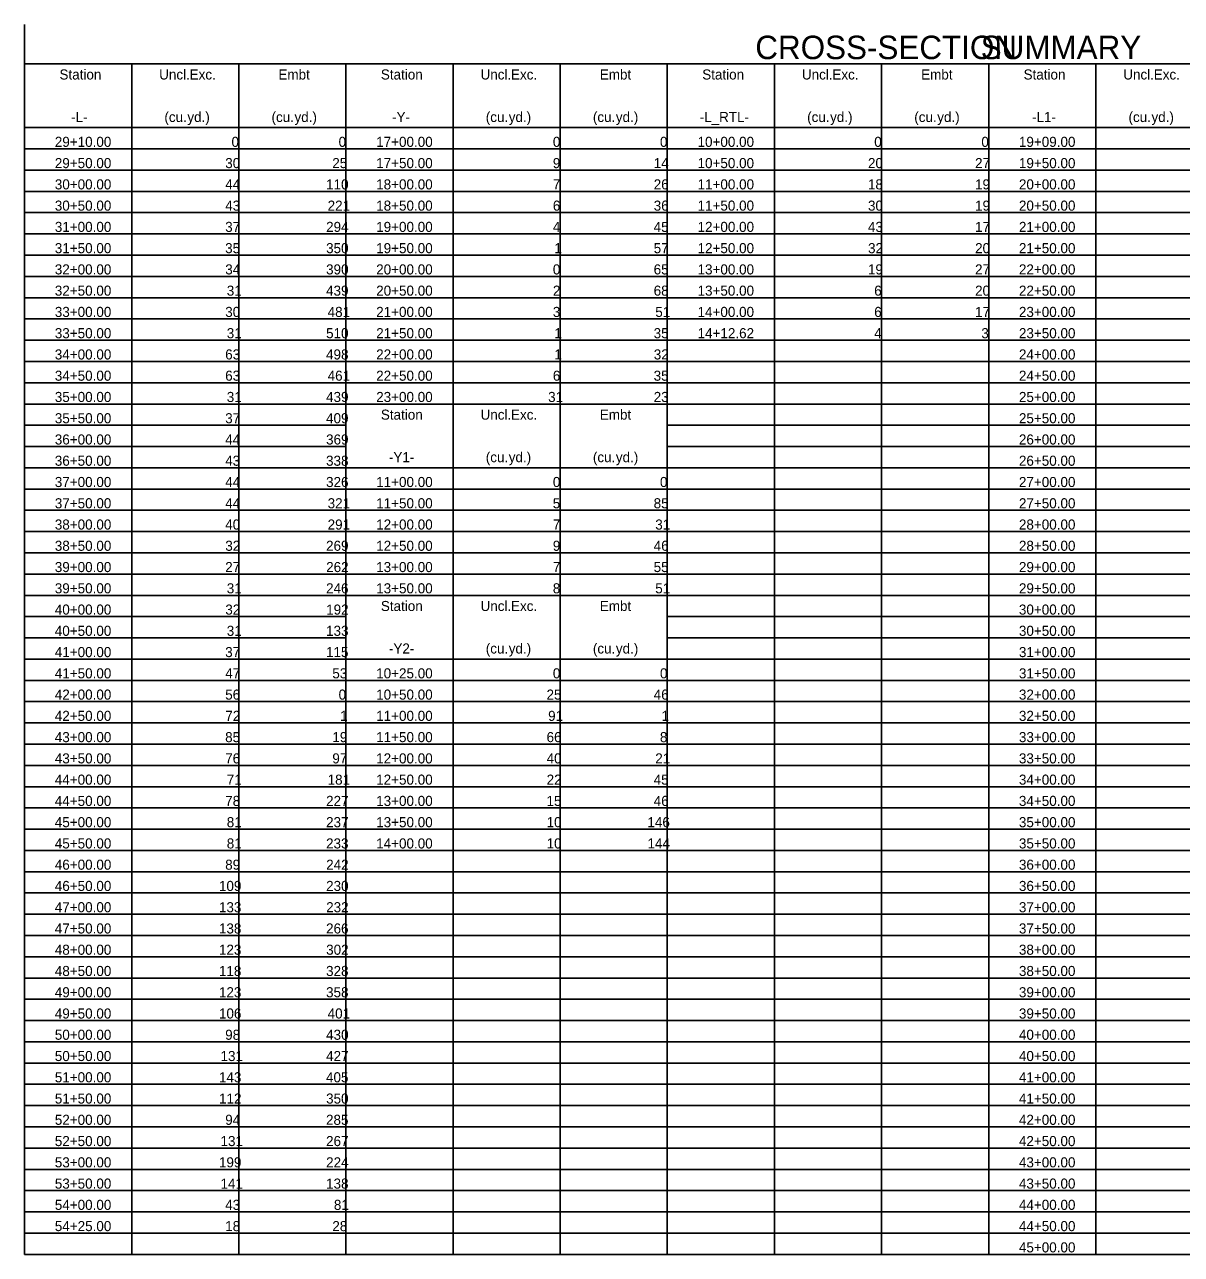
# Model space of a CAD drawing. Extents: x 239 to 408, y 686 to 906.
# Drawn here: x 256.1 to 346.1, y 686 to 781.7 of the extents above; entities that cross this region are included whole.
import ezdxf

# ---------------------------------------------------------------- set-up
doc = ezdxf.new("R2010")
doc.units = 0
doc.layers.add('Default', color=7, linetype='Continuous')

msp = doc.modelspace()

# ---------------------------------------------------------------- linework, layer by layer
at = {"layer": 'Default'}
for p, q in [((256.088, 781.713), (256.088, 781.713)), ((256.088, 778.659), (256.088, 781.713)), ((256.088, 778.659), (406.087, 778.659)), ((256.088, 686.039), (256.088, 778.659)), ((264.421, 686.039), (264.421, 778.659)), ((272.755, 686.039), (272.755, 778.659)), ((272.755, 686.039), (272.755, 778.659)), ((281.088, 686.039), (281.088, 778.659)), ((289.421, 686.039), (289.421, 778.659)), ((297.755, 686.039), (297.755, 778.659)), ((306.088, 686.039), (306.088, 778.659)), ((306.088, 686.039), (306.088, 778.659)), ((314.421, 686.039), (314.421, 778.659)), ((322.754, 686.039), (322.754, 778.659)), ((331.088, 686.039), (331.088, 778.659)), ((339.421, 686.039), (339.421, 778.659)), ((339.421, 686.039), (339.421, 778.659)), ((256.088, 773.697), (406.087, 773.697)), ((256.088, 772.043), (406.087, 772.043)), ((256.088, 770.39), (406.087, 770.39)), ((256.088, 768.736), (406.087, 768.736)), ((256.088, 767.082), (406.087, 767.082)), ((256.088, 765.428), (406.087, 765.428)), ((256.088, 763.774), (406.087, 763.774)), ((256.088, 762.12), (406.087, 762.12)), ((256.088, 760.466), (406.087, 760.466)), ((256.088, 758.812), (406.087, 758.812)), ((256.088, 757.158), (406.087, 757.158)), ((256.088, 755.504), (406.087, 755.504)), ((256.088, 753.85), (381.087, 753.85)), ((256.088, 752.196), (281.088, 752.196)), ((281.088, 752.196), (306.088, 752.196)), ((306.088, 752.196), (381.087, 752.196)), ((256.088, 750.542), (281.088, 750.542)), ((306.088, 750.542), (406.087, 750.542)), ((256.088, 748.888), (281.088, 748.888)), ((306.088, 748.888), (406.087, 748.888)), ((256.088, 747.234), (281.088, 747.234)), ((281.088, 747.234), (306.088, 747.234)), ((306.088, 747.234), (406.087, 747.234)), ((256.088, 745.581), (406.087, 745.581)), ((256.088, 743.927), (406.087, 743.927)), ((256.088, 742.273), (406.087, 742.273)), ((256.088, 740.619), (406.087, 740.619)), ((256.088, 738.965), (406.087, 738.965)), ((256.088, 737.311), (281.088, 737.311)), ((281.088, 737.311), (306.088, 737.311)), ((306.088, 737.311), (406.087, 737.311)), ((256.088, 735.657), (281.088, 735.657)), ((306.088, 735.657), (406.087, 735.657)), ((256.088, 734.003), (281.088, 734.003)), ((306.088, 734.003), (406.087, 734.003)), ((256.088, 732.349), (281.088, 732.349)), ((281.088, 732.349), (306.088, 732.349)), ((306.088, 732.349), (406.087, 732.349)), ((256.088, 730.695), (406.087, 730.695)), ((256.088, 729.041), (406.087, 729.041)), ((256.088, 727.387), (406.087, 727.387)), ((256.088, 725.733), (406.087, 725.733)), ((256.088, 724.079), (406.087, 724.079)), ((256.088, 722.425), (406.087, 722.425)), ((256.088, 720.771), (406.087, 720.771)), ((256.088, 719.118), (406.087, 719.118)), ((256.088, 717.464), (406.087, 717.464)), ((256.088, 715.81), (406.087, 715.81)), ((256.088, 714.156), (406.087, 714.156)), ((256.088, 712.502), (406.087, 712.502)), ((256.088, 710.848), (406.087, 710.848)), ((256.088, 709.194), (406.087, 709.194)), ((256.088, 707.54), (381.087, 707.54)), ((256.088, 705.886), (381.087, 705.886)), ((256.088, 704.232), (406.087, 704.232)), ((256.088, 702.578), (406.087, 702.578)), ((256.088, 700.924), (406.087, 700.924)), ((256.088, 699.27), (406.087, 699.27)), ((256.088, 697.616), (406.087, 697.616)), ((256.088, 695.962), (406.087, 695.962)), ((256.088, 694.309), (406.087, 694.309)), ((256.088, 692.655), (406.087, 692.655)), ((256.088, 691.001), (406.087, 691.001)), ((256.088, 689.347), (406.087, 689.347)), ((256.088, 687.693), (406.087, 687.693)), ((256.088, 686.039), (406.087, 686.039))]:
    msp.add_line(p, q, dxfattribs=at)

# ---------------------------------------------------------------- texts
for s, height, p in [('CROSS-SECTION', 1.82683, (312.932, 779.025)), (' SUMMARY', 1.8268, (329.788, 779.025)), ('Station', 0.7829, (258.802, 777.441)), ('Uncl.', 0.7829, (266.557, 777.441)), (' Exc.', 0.7829, (268.636, 777.441)), ('Embt', 0.7829, (275.833, 777.441)), ('Station', 0.7829, (283.802, 777.441)), ('Uncl.', 0.7829, (291.557, 777.441)), (' Exc.', 0.7829, (293.636, 777.441)), ('Embt', 0.7829, (300.833, 777.441)), ('Station', 0.7829, (308.802, 777.441)), ('Uncl.', 0.7829, (316.557, 777.441)), (' Exc.', 0.7829, (318.636, 777.441)), ('Embt', 0.7829, (325.832, 777.441)), ('Station', 0.7829, (333.801, 777.441)), ('Uncl.', 0.7829, (341.557, 777.441)), (' Exc.', 0.7829, (343.636, 777.441)), ('-L-', 0.7829, (259.699, 774.133)), ('(cu.', 0.7829, (266.964, 774.133)), (' yd.)', 0.7829, (268.459, 774.133)), ('(cu.', 0.7829, (275.297, 774.133)), (' yd.)', 0.7829, (276.792, 774.133)), ('-Y-', 0.7829, (284.675, 774.133)), ('(cu.', 0.7829, (291.964, 774.133)), (' yd.)', 0.7829, (293.459, 774.133)), ('(cu.', 0.7829, (300.297, 774.133)), (' yd.)', 0.7829, (301.792, 774.133)), ('-L_RTL-', 0.7829, (308.605, 774.133)), ('(cu.', 0.7829, (316.964, 774.133)), (' yd.)', 0.7829, (318.459, 774.133)), ('(cu.', 0.7829, (325.297, 774.133)), (' yd.)', 0.7829, (326.792, 774.133)), ('-L1-', 0.7829, (334.456, 774.133)), ('(cu.', 0.7829, (341.964, 774.133)), (' yd.)', 0.7829, (343.459, 774.133)), ('29+10.00', 0.7829, (258.439, 772.2)), ('0', 0.783, (272.183, 772.2)), ('0', 0.783, (280.516, 772.2)), ('17+00.00', 0.7829, (283.439, 772.2)), ('0', 0.783, (297.183, 772.2)), ('0', 0.783, (305.516, 772.2)), ('10+00.00', 0.7829, (308.439, 772.2)), ('0', 0.783, (322.183, 772.2)), ('0', 0.783, (330.516, 772.2)), ('19+09.00', 0.7829, (333.439, 772.2)), ('29+50.00', 0.7829, (258.439, 770.546)), ('30', 0.7829, (271.697, 770.546)), ('25', 0.7829, (280.023, 770.546)), ('17+50.00', 0.7829, (283.439, 770.546)), ('9', 0.783, (297.18, 770.546)), ('14', 0.7829, (305.03, 770.546)), ('10+50.00', 0.7829, (308.439, 770.546)), ('20', 0.7829, (321.696, 770.546)), ('27', 0.7829, (330.027, 770.546)), ('19+50.00', 0.7829, (333.439, 770.546)), ('30+00.00', 0.7829, (258.439, 768.892)), ('44', 0.7829, (271.697, 768.892)), ('110', 0.7829, (279.543, 768.892)), ('18+00.00', 0.7829, (283.439, 768.892)), ('7', 0.783, (297.181, 768.892)), ('26', 0.7829, (305.027, 768.892)), ('11+00.00', 0.7829, (308.439, 768.892)), ('18', 0.7829, (321.693, 768.892)), ('19', 0.7829, (330.026, 768.892)), ('20+00.00', 0.7829, (333.439, 768.892)), ('30+50.00', 0.7829, (258.439, 767.238)), ('43', 0.7829, (271.694, 767.238)), ('221', 0.7829, (279.662, 767.238)), ('18+50.00', 0.7829, (283.439, 767.238)), ('6', 0.783, (297.181, 767.238)), ('36', 0.7829, (305.027, 767.238)), ('11+50.00', 0.7829, (308.439, 767.238)), ('30', 0.7829, (321.696, 767.238)), ('19', 0.7829, (330.026, 767.238)), ('20+50.00', 0.7829, (333.439, 767.238)), ('31+00.00', 0.7829, (258.439, 765.584)), ('37', 0.7829, (271.694, 765.584)), ('294', 0.7829, (279.544, 765.584)), ('19+00.00', 0.7829, (283.439, 765.584)), ('4', 0.783, (297.183, 765.584)), ('45', 0.7829, (305.023, 765.584)), ('12+00.00', 0.7829, (308.439, 765.584)), ('43', 0.7829, (321.694, 765.584)), ('17', 0.7829, (330.027, 765.584)), ('21+00.00', 0.7829, (333.439, 765.584)), ('31+50.00', 0.7829, (258.439, 763.93)), ('35', 0.7829, (271.689, 763.93)), ('350', 0.7829, (279.543, 763.93)), ('19+50.00', 0.7829, (283.439, 763.93)), ('1', 0.783, (297.302, 763.93)), ('57', 0.7829, (305.027, 763.93)), ('12+50.00', 0.7829, (308.439, 763.93)), ('32', 0.7829, (321.701, 763.93)), ('20', 0.7829, (330.03, 763.93)), ('21+50.00', 0.7829, (333.439, 763.93)), ('32+00.00', 0.7829, (258.439, 762.276)), ('34', 0.7829, (271.697, 762.276)), ('390', 0.7829, (279.543, 762.276)), ('20+00.00', 0.7829, (283.439, 762.276)), ('0', 0.783, (297.183, 762.276)), ('65', 0.7829, (305.023, 762.276)), ('13+00.00', 0.7829, (308.439, 762.276)), ('19', 0.7829, (321.693, 762.276)), ('27', 0.7829, (330.027, 762.276)), ('22+00.00', 0.7829, (333.439, 762.276)), ('32+50.00', 0.7829, (258.439, 760.623)), ('31', 0.7829, (271.815, 760.623)), ('439', 0.7829, (279.54, 760.623)), ('20+50.00', 0.7829, (283.439, 760.623)), ('2', 0.783, (297.187, 760.623)), ('68', 0.7829, (305.026, 760.623)), ('13+50.00', 0.7829, (308.439, 760.623)), ('6', 0.783, (322.18, 760.623)), ('20', 0.7829, (330.03, 760.623)), ('22+50.00', 0.7829, (333.439, 760.623)), ('33+00.00', 0.7829, (258.439, 758.969)), ('30', 0.7829, (271.697, 758.969)), ('481', 0.7829, (279.662, 758.969)), ('21+00.00', 0.7829, (283.439, 758.969)), ('3', 0.783, (297.181, 758.969)), ('51', 0.7829, (305.149, 758.969)), ('14+00.00', 0.7829, (308.439, 758.969)), ('6', 0.783, (322.18, 758.969)), ('17', 0.7829, (330.027, 758.969)), ('23+00.00', 0.7829, (333.439, 758.969)), ('33+50.00', 0.7829, (258.439, 757.315)), ('31', 0.7829, (271.815, 757.315)), ('510', 0.7829, (279.543, 757.315)), ('21+50.00', 0.7829, (283.439, 757.315)), ('1', 0.783, (297.302, 757.315)), ('35', 0.7829, (305.023, 757.315)), ('14+12.62', 0.7829, (308.441, 757.315)), ('4', 0.783, (322.183, 757.315)), ('3', 0.783, (330.514, 757.315)), ('23+50.00', 0.7829, (333.439, 757.315)), ('34+00.00', 0.7829, (258.439, 755.661)), ('63', 0.7829, (271.694, 755.661)), ('498', 0.7829, (279.54, 755.661)), ('22+00.00', 0.7829, (283.439, 755.661)), ('1', 0.783, (297.302, 755.661)), ('32', 0.7829, (305.034, 755.661)), ('24+00.00', 0.7829, (333.439, 755.661)), ('34+50.00', 0.7829, (258.439, 754.007)), ('63', 0.7829, (271.694, 754.007)), ('461', 0.7829, (279.662, 754.007)), ('22+50.00', 0.7829, (283.439, 754.007)), ('6', 0.783, (297.181, 754.007)), ('35', 0.7829, (305.023, 754.007)), ('24+50.00', 0.7829, (333.439, 754.007)), ('35+00.00', 0.7829, (258.439, 752.353)), ('31', 0.7829, (271.815, 752.353)), ('439', 0.7829, (279.54, 752.353)), ('23+00.00', 0.7829, (283.439, 752.353)), ('31', 0.7829, (296.815, 752.353)), ('23', 0.7829, (305.027, 752.353)), ('25+00.00', 0.7829, (333.439, 752.353)), ('35+50.00', 0.7829, (258.439, 750.699)), ('37', 0.7829, (271.694, 750.699)), ('409', 0.7829, (279.54, 750.699)), ('Station', 0.7829, (283.802, 750.978)), ('Uncl.', 0.7829, (291.557, 750.978)), (' Exc.', 0.7829, (293.636, 750.978)), ('Embt', 0.7829, (300.833, 750.978)), ('25+50.00', 0.7829, (333.439, 750.699)), ('36+00.00', 0.7829, (258.439, 749.045)), ('44', 0.7829, (271.697, 749.045)), ('369', 0.7829, (279.54, 749.045)), ('26+00.00', 0.7829, (333.439, 749.045)), ('36+50.00', 0.7829, (258.439, 747.391)), ('43', 0.7829, (271.694, 747.391)), ('338', 0.7829, (279.54, 747.391)), ('-Y1-', 0.7829, (284.431, 747.67)), ('(cu.', 0.7829, (291.964, 747.67)), (' yd.)', 0.7829, (293.459, 747.67)), ('(cu.', 0.7829, (300.297, 747.67)), (' yd.)', 0.7829, (301.792, 747.67)), ('26+50.00', 0.7829, (333.439, 747.391)), ('37+00.00', 0.7829, (258.439, 745.737)), ('44', 0.7829, (271.697, 745.737)), ('326', 0.7829, (279.541, 745.737)), ('11+00.00', 0.7829, (283.439, 745.737)), ('0', 0.783, (297.183, 745.737)), ('0', 0.783, (305.516, 745.737)), ('27+00.00', 0.7829, (333.439, 745.737)), ('37+50.00', 0.7829, (258.439, 744.083)), ('44', 0.7829, (271.697, 744.083)), ('321', 0.7829, (279.662, 744.083)), ('11+50.00', 0.7829, (283.439, 744.083)), ('5', 0.783, (297.176, 744.083)), ('85', 0.7829, (305.023, 744.083)), ('27+50.00', 0.7829, (333.439, 744.083)), ('38+00.00', 0.7829, (258.439, 742.429)), ('40', 0.7829, (271.697, 742.429)), ('291', 0.7829, (279.662, 742.429)), ('12+00.00', 0.7829, (283.439, 742.429)), ('7', 0.783, (297.181, 742.429)), ('31', 0.7829, (305.149, 742.429)), ('28+00.00', 0.7829, (333.439, 742.429)), ('38+50.00', 0.7829, (258.439, 740.775)), ('32', 0.7829, (271.701, 740.775)), ('269', 0.7829, (279.54, 740.775)), ('12+50.00', 0.7829, (283.439, 740.775)), ('9', 0.783, (297.18, 740.775)), ('46', 0.7829, (305.027, 740.775)), ('28+50.00', 0.7829, (333.439, 740.775)), ('39+00.00', 0.7829, (258.439, 739.121)), ('27', 0.7829, (271.694, 739.121)), ('262', 0.7829, (279.548, 739.121)), ('13+00.00', 0.7829, (283.439, 739.121)), ('7', 0.783, (297.181, 739.121)), ('55', 0.7829, (305.023, 739.121)), ('29+00.00', 0.7829, (333.439, 739.121)), ('39+50.00', 0.7829, (258.439, 737.467)), ('31', 0.7829, (271.815, 737.467)), ('246', 0.7829, (279.541, 737.467)), ('13+50.00', 0.7829, (283.439, 737.467)), ('8', 0.783, (297.18, 737.467)), ('51', 0.7829, (305.149, 737.467)), ('29+50.00', 0.7829, (333.439, 737.467)), ('Station', 0.7829, (283.802, 736.092)), ('Uncl.', 0.7829, (291.557, 736.092)), (' Exc.', 0.7829, (293.636, 736.092)), ('Embt', 0.7829, (300.833, 736.092)), ('40+00.00', 0.7829, (258.439, 735.813)), ('32', 0.7829, (271.701, 735.813)), ('192', 0.7829, (279.548, 735.813)), ('30+00.00', 0.7829, (333.439, 735.813)), ('40+50.00', 0.7829, (258.439, 734.16)), ('31', 0.7829, (271.815, 734.16)), ('133', 0.7829, (279.541, 734.16)), ('30+50.00', 0.7829, (333.439, 734.16)), ('41+00.00', 0.7829, (258.439, 732.506)), ('37', 0.7829, (271.694, 732.506)), ('115', 0.7829, (279.536, 732.506)), ('-Y2-', 0.7829, (284.431, 732.785)), ('(cu.', 0.7829, (291.964, 732.785)), (' yd.)', 0.7829, (293.459, 732.785)), ('(cu.', 0.7829, (300.297, 732.785)), (' yd.)', 0.7829, (301.792, 732.785)), ('31+00.00', 0.7829, (333.439, 732.506)), ('41+50.00', 0.7829, (258.439, 730.852)), ('47', 0.7829, (271.694, 730.852)), ('53', 0.7829, (280.027, 730.852)), ('10+25.00', 0.7829, (283.439, 730.852)), ('0', 0.783, (297.183, 730.852)), ('0', 0.783, (305.516, 730.852)), ('31+50.00', 0.7829, (333.439, 730.852)), ('42+00.00', 0.7829, (258.439, 729.198)), ('56', 0.7829, (271.694, 729.198)), ('0', 0.783, (280.516, 729.198)), ('10+50.00', 0.7829, (283.439, 729.198)), ('25', 0.7829, (296.689, 729.198)), ('46', 0.7829, (305.027, 729.198)), ('32+00.00', 0.7829, (333.439, 729.198)), ('42+50.00', 0.7829, (258.439, 727.544)), ('72', 0.7829, (271.701, 727.544)), ('1', 0.783, (280.635, 727.544)), ('11+00.00', 0.7829, (283.439, 727.544)), ('91', 0.7829, (296.815, 727.544)), ('1', 0.783, (305.635, 727.544)), ('32+50.00', 0.7829, (333.439, 727.544)), ('43+00.00', 0.7829, (258.439, 725.89)), ('85', 0.7829, (271.689, 725.89)), ('19', 0.7829, (280.027, 725.89)), ('11+50.00', 0.7829, (283.439, 725.89)), ('66', 0.7829, (296.694, 725.89)), ('8', 0.783, (305.513, 725.89)), ('33+00.00', 0.7829, (333.439, 725.89)), ('43+50.00', 0.7829, (258.439, 724.236)), ('76', 0.7829, (271.694, 724.236)), ('97', 0.7829, (280.027, 724.236)), ('12+00.00', 0.7829, (283.439, 724.236)), ('40', 0.7829, (296.696, 724.236)), ('21', 0.7829, (305.149, 724.236)), ('33+50.00', 0.7829, (333.439, 724.236)), ('44+00.00', 0.7829, (258.439, 722.582)), ('71', 0.7829, (271.815, 722.582)), ('181', 0.7829, (279.662, 722.582)), ('12+50.00', 0.7829, (283.439, 722.582)), ('22', 0.7829, (296.701, 722.582)), ('45', 0.7829, (305.023, 722.582)), ('34+00.00', 0.7829, (333.439, 722.582)), ('44+50.00', 0.7829, (258.439, 720.928)), ('78', 0.7829, (271.693, 720.928)), ('227', 0.7829, (279.541, 720.928)), ('13+00.00', 0.7829, (283.439, 720.928)), ('15', 0.7829, (296.689, 720.928)), ('46', 0.7829, (305.027, 720.928)), ('34+50.00', 0.7829, (333.439, 720.928)), ('45+00.00', 0.7829, (258.439, 719.274)), ('81', 0.7829, (271.815, 719.274)), ('237', 0.7829, (279.541, 719.274)), ('13+50.00', 0.7829, (283.439, 719.274)), ('10', 0.7829, (296.696, 719.274)), ('146', 0.7829, (304.541, 719.274)), ('35+00.00', 0.7829, (333.439, 719.274)), ('45+50.00', 0.7829, (258.439, 717.62)), ('81', 0.7829, (271.815, 717.62)), ('233', 0.7829, (279.541, 717.62)), ('14+00.00', 0.7829, (283.439, 717.62)), ('10', 0.7829, (296.696, 717.62)), ('144', 0.7829, (304.544, 717.62)), ('35+50.00', 0.7829, (333.439, 717.62)), ('46+00.00', 0.7829, (258.439, 715.966)), ('89', 0.7829, (271.693, 715.966)), ('242', 0.7829, (279.548, 715.966)), ('36+00.00', 0.7829, (333.439, 715.966)), ('46+50.00', 0.7829, (258.439, 714.312)), ('109', 0.7829, (271.207, 714.312)), ('230', 0.7829, (279.543, 714.312)), ('36+50.00', 0.7829, (333.439, 714.312)), ('47+00.00', 0.7829, (258.439, 712.658)), ('133', 0.7829, (271.208, 712.658)), ('232', 0.7829, (279.548, 712.658)), ('37+00.00', 0.7829, (333.439, 712.658)), ('47+50.00', 0.7829, (258.439, 711.004)), ('138', 0.7829, (271.207, 711.004)), ('266', 0.7829, (279.541, 711.004)), ('37+50.00', 0.7829, (333.439, 711.004)), ('48+00.00', 0.7829, (258.439, 709.351)), ('123', 0.7829, (271.208, 709.351)), ('302', 0.7829, (279.548, 709.351)), ('38+00.00', 0.7829, (333.439, 709.351)), ('48+50.00', 0.7829, (258.439, 707.697)), ('118', 0.7829, (271.207, 707.697)), ('328', 0.7829, (279.54, 707.697)), ('38+50.00', 0.7829, (333.439, 707.697)), ('49+00.00', 0.7829, (258.439, 706.043)), ('123', 0.7829, (271.208, 706.043)), ('358', 0.7829, (279.54, 706.043)), ('39+00.00', 0.7829, (333.439, 706.043)), ('49+50.00', 0.7829, (258.439, 704.389)), ('106', 0.7829, (271.208, 704.389)), ('401', 0.7829, (279.662, 704.389)), ('39+50.00', 0.7829, (333.439, 704.389)), ('50+00.00', 0.7829, (258.439, 702.735)), ('98', 0.7829, (271.693, 702.735)), ('430', 0.7829, (279.543, 702.735)), ('40+00.00', 0.7829, (333.439, 702.735)), ('50+50.00', 0.7829, (258.439, 701.081)), ('131', 0.7829, (271.329, 701.081)), ('427', 0.7829, (279.541, 701.081)), ('40+50.00', 0.7829, (333.439, 701.081)), ('51+00.00', 0.7829, (258.439, 699.427)), ('143', 0.7829, (271.208, 699.427)), ('405', 0.7829, (279.536, 699.427)), ('41+00.00', 0.7829, (333.439, 699.427)), ('51+50.00', 0.7829, (258.439, 697.773)), ('112', 0.7829, (271.214, 697.773)), ('350', 0.7829, (279.543, 697.773)), ('41+50.00', 0.7829, (333.439, 697.773)), ('52+00.00', 0.7829, (258.439, 696.119)), ('94', 0.7829, (271.697, 696.119)), ('285', 0.7829, (279.536, 696.119)), ('42+00.00', 0.7829, (333.439, 696.119)), ('52+50.00', 0.7829, (258.439, 694.465)), ('131', 0.7829, (271.329, 694.465)), ('267', 0.7829, (279.541, 694.465)), ('42+50.00', 0.7829, (333.439, 694.465)), ('53+00.00', 0.7829, (258.439, 692.811)), ('199', 0.7829, (271.207, 692.811)), ('224', 0.7829, (279.544, 692.811)), ('43+00.00', 0.7829, (333.439, 692.811)), ('53+50.00', 0.7829, (258.439, 691.157)), ('141', 0.7829, (271.329, 691.157)), ('138', 0.7829, (279.54, 691.157)), ('43+50.00', 0.7829, (333.439, 691.157)), ('54+00.00', 0.7829, (258.439, 689.503)), ('43', 0.7829, (271.694, 689.503)), ('81', 0.7829, (280.149, 689.503)), ('44+00.00', 0.7829, (333.439, 689.503)), ('54+25.00', 0.7829, (258.439, 687.849)), ('18', 0.7829, (271.693, 687.849)), ('28', 0.7829, (280.027, 687.849)), ('44+50.00', 0.7829, (333.439, 687.849)), ('45+00.00', 0.7829, (333.439, 686.195))]:
    msp.add_text(s, height=height, dxfattribs=at).set_placement(p)

doc.saveas('drawing.dxf')
